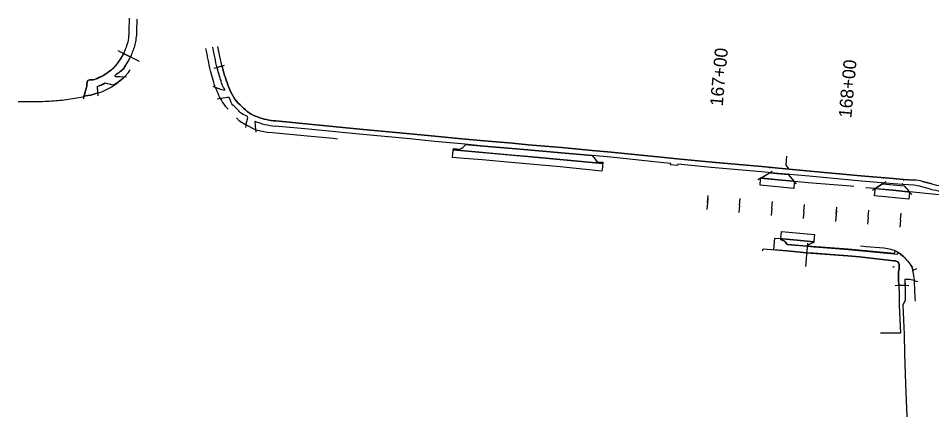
# Model space of a CAD drawing. Extents: x 20499880 to 20505309, y 7953507 to 7955507.
# Drawn here: x 20499880 to 20500587, y 7953843 to 7954151 of the extents above; entities that cross this region are included whole.
import ezdxf

# ---------------------------------------------------------------- set-up
doc = ezdxf.new("R2010")
doc.units = 0
for name, color, linetype in [('Alignment', 7, 'Continuous'), ('Curb', 7, 'Continuous'), ('Draft_0', 7, 'Continuous'), ('Draft_7', 7, 'Continuous'), ('EdgePaved', 7, 'Continuous'), ('Entrance', 7, 'Continuous')]:
    doc.layers.add(name, color=color, linetype=linetype)

msp = doc.modelspace()

# ---------------------------------------------------------------- linework, layer by layer
at = {"layer": 'Alignment'}
for p, q in [((20500413.4, 7954008.91), (20500413.9, 7954014.35)), ((20500413.4, 7954008.91), (20500412.91, 7954003.47)), ((20500512.99, 7953999.8), (20500513.49, 7954005.24)), ((20500512.99, 7953999.8), (20500512.49, 7953994.36))]:
    msp.add_line(p, q, dxfattribs=at)
at = {"layer": 'Curb'}
for p, q in [((20499973.8, 7954117.93), (20499957.3, 7954126.26)), ((20500031.67, 7954112.87), (20500039.61, 7954115.18)), ((20500032.78, 7954097.95), (20500031.03, 7954098.58)), ((20500033.16, 7954096.5), (20500032.53, 7954098.14)), ((20500032.78, 7954097.95), (20500036.7, 7954096.53)), ((20500036.7, 7954096.53), (20500039.61, 7954095.78)), ((20500036.59, 7954089.25), (20500034.08, 7954088.79)), ((20500036.43, 7954089.27), (20500035.86, 7954090.38)), ((20500038.72, 7954089.64), (20500036.59, 7954089.25)), ((20500042.12, 7954090.26), (20500038.72, 7954089.64)), ((20500042.47, 7954081.07), (20500040.13, 7954083.51)), ((20500051.42, 7954071.89), (20500048.99, 7954074.45)), ((20500057.07, 7954071.57), (20500057.64, 7954074.45)), ((20500056.14, 7954068.86), (20500051.42, 7954071.89)), ((20500056.35, 7954068.9), (20500055.82, 7954066.93)), ((20500057.16, 7954068.38), (20500056.14, 7954068.86)), ((20500056.35, 7954068.9), (20500057.07, 7954071.57)), ((20500062.62, 7954065.74), (20500057.16, 7954068.38)), ((20500063.19, 7954071.79), (20500063.48, 7954068.16)), ((20500063.48, 7954068.16), (20500063.67, 7954065.44)), ((20500104.81, 7954065.58), (20500078.93, 7954068.03)), ((20500105.19, 7954069.47), (20500079.37, 7954072)), ((20500144.47, 7954065.69), (20500105.19, 7954069.47)), ((20500063.89, 7954065.16), (20500062.62, 7954065.74)), ((20500063.67, 7954065.44), (20500063.81, 7954063.4)), ((20500103.94, 7954060.16), (20500073.94, 7954063.02)), ((20500123.68, 7954058.39), (20500103.94, 7954060.16)), ((20500143.94, 7954061.83), (20500104.81, 7954065.58)), ((20500183.22, 7954058.05), (20500143.94, 7954061.83)), ((20500183.41, 7954062.13), (20500144.47, 7954065.69)), ((20500202.59, 7954060.17), (20500183.41, 7954062.13)), ((20500223.4, 7954058.24), (20500202.59, 7954060.17)), ((20500127.04, 7954058.02), (20500123.68, 7954058.39)), ((20500202.08, 7954056.17), (20500183.22, 7954058.05)), ((20500222.99, 7954054.19), (20500202.08, 7954056.17)), ((20500240.36, 7954052.62), (20500222.99, 7954054.19)), ((20500240.64, 7954056.62), (20500223.4, 7954058.24)), ((20500262.34, 7954050.65), (20500240.36, 7954052.62)), ((20500262.67, 7954054.79), (20500240.64, 7954056.62)), ((20500274.82, 7954053.54), (20500262.67, 7954054.79)), ((20500300.6, 7954051.37), (20500274.82, 7954053.54)), ((20500274.47, 7954049.57), (20500262.34, 7954050.65)), ((20500300.21, 7954047.31), (20500274.47, 7954049.57)), ((20500324.26, 7954045.4), (20500300.21, 7954047.31)), ((20500324.26, 7954049.21), (20500300.6, 7954051.37)), ((20500338.83, 7954047.76), (20500324.26, 7954049.21)), ((20500338.58, 7954043.89), (20500324.26, 7954045.4)), ((20500377.6, 7954043.89), (20500338.83, 7954047.76)), ((20500377.05, 7954039.84), (20500338.58, 7954043.89)), ((20500385.03, 7954039), (20500377.05, 7954039.84)), ((20500389.99, 7954042.67), (20500377.6, 7954043.89)), ((20500384.97, 7954038.02), (20500385.03, 7954039)), ((20500390.36, 7954037.49), (20500384.97, 7954038.02)), ((20500417.16, 7954040.21), (20500389.99, 7954042.67)), ((20500390.47, 7954038.55), (20500390.36, 7954037.49)), ((20500416.2, 7954036.12), (20500390.47, 7954038.55)), ((20500455.59, 7954036.74), (20500417.16, 7954040.21)), ((20500455.25, 7954032.56), (20500416.2, 7954036.12)), ((20500468.08, 7954031.37), (20500455.25, 7954032.56)), ((20500468.45, 7954035.45), (20500455.59, 7954036.74)), ((20500461.79, 7954036.23), (20500461.15, 7954035.57)), ((20500461.35, 7954031.96), (20500463.43, 7954033.24)), ((20500492.18, 7954029.29), (20500468.08, 7954031.37)), ((20500493.03, 7954033.23), (20500468.45, 7954035.45)), ((20500476.15, 7954030.5), (20500475.41, 7954031.38)), ((20500532.19, 7954029.67), (20500493.03, 7954033.23)), ((20500454.94, 7954028.04), (20500452.54, 7954026.57)), ((20500480.35, 7954025.5), (20500482.16, 7954023.35)), ((20500532.7, 7954025.55), (20500492.18, 7954029.29)), ((20500557.13, 7954027.54), (20500532.19, 7954029.67)), ((20500557.3, 7954023.46), (20500532.7, 7954025.55)), ((20500550.15, 7954028.26), (20500549.36, 7954027.43)), ((20500549.91, 7954024.04), (20500551.64, 7954025.19)), ((20500565.04, 7954026.81), (20500557.13, 7954027.54)), ((20500564.78, 7954022.72), (20500564.01, 7954023.57)), ((20500564.77, 7954026.99), (20500565.43, 7954026.05)), ((20500573.38, 7954026.23), (20500565.04, 7954026.81)), ((20500587.01, 7954023.29), (20500579.82, 7954025.19)), ((20500543.62, 7954019.86), (20500541.28, 7954018.31)), ((20500564.94, 7954022.82), (20500557.3, 7954023.46)), ((20500573.1, 7954022.26), (20500564.94, 7954022.82)), ((20500568.87, 7954018.17), (20500571.53, 7954015.21)), ((20500577.5, 7954021.59), (20500573.1, 7954022.26)), ((20500586.09, 7954019.36), (20500577.5, 7954021.59)), ((20500490.97, 7953977.4), (20500489.33, 7953959.44)), ((20500531.92, 7953975.36), (20500536.23, 7953974.92)), ((20500536.23, 7953974.92), (20500549.98, 7953973.78)), ((20500456, 7953971.64), (20500456.34, 7953972.2)), ((20500456.34, 7953972.2), (20500456.45, 7953973.11)), ((20500456.45, 7953973.11), (20500475.07, 7953971.56)), ((20500475.07, 7953971.56), (20500482.57, 7953970.9)), ((20500482.57, 7953970.9), (20500490.05, 7953970.1)), ((20500490.05, 7953970.1), (20500522.01, 7953967.81)), ((20500522.01, 7953967.81), (20500531.04, 7953966.92)), ((20500531.04, 7953966.92), (20500557.8, 7953963.96)), ((20500561.69, 7953957.72), (20500561.21, 7953955.33)), ((20500561.21, 7953955.33), (20500561.32, 7953949.28)), ((20500572.01, 7953956.44), (20500575.46, 7953957.86)), ((20500572.25, 7953956.44), (20500572.35, 7953955.51)), ((20500572.35, 7953955.51), (20500572.96, 7953952.35)), ((20500561.32, 7953949.28), (20500561.72, 7953938.86)), ((20500572.96, 7953952.35), (20500573.33, 7953949.21)), ((20500573.09, 7953948.62), (20500576.06, 7953947.85)), ((20500573.33, 7953949.21), (20500573.45, 7953948.21)), ((20500573.45, 7953948.21), (20500573.75, 7953940.98)), ((20500569.28, 7953944.81), (20500558.8, 7953944.62)), ((20500561.72, 7953938.86), (20500561.68, 7953929.64)), ((20500573.75, 7953940.98), (20500574, 7953935.24)), ((20500574, 7953935.24), (20500574.22, 7953932.67)), ((20500561.68, 7953929.64), (20500562.76, 7953907.89)), ((20500555.42, 7953907.84), (20500547.33, 7953907.89)), ((20500562.76, 7953907.89), (20500555.42, 7953907.84))]:
    msp.add_line(p, q, dxfattribs=at)
for points in [[(20500324.26, 7954045.4), (20500326.47, 7954042.35), (20500328.82, 7954039.39)], [(20500474.63, 7954044.83), (20500474.23, 7954037.76), (20500476.42, 7954034.69)], [(20500454.94, 7954028.04), (20500461.43, 7954032.01)], [(20500526.74, 7954021.19), (20500524.04, 7954021.59), (20500491.47, 7954024.2), (20500480.9, 7954025.2), (20500479.73, 7954025.35), (20500468.26, 7954026.53), (20500455.73, 7954027.79), (20500454.64, 7954027.86)], [(20500549.91, 7954024.04), (20500543.62, 7954019.86)], [(20500623.83, 7954012.28), (20500622.74, 7954012.45), (20500617.71, 7954012.79), (20500616.66, 7954012.91), (20500590.17, 7954015.26), (20500569.77, 7954017.16), (20500568.64, 7954017.31), (20500556.84, 7954018.48), (20500544.21, 7954019.57), (20500543.25, 7954019.65), (20500536.01, 7954020.3)], [(20500558.83, 7953971.56), (20500557.92, 7953969.58), (20500522.44, 7953972.83), (20500522.44, 7953972.83), (20500522.44, 7953972.83), (20500490.76, 7953975.14)], [(20500573.09, 7953948.62), (20500570.05, 7953949.41), (20500566.23, 7953949.36), (20500566.49, 7953938.8), (20500566.55, 7953933.52), (20500564.62, 7953929.64), (20500565.79, 7953906.99), (20500565.86, 7953892.06), (20500566.7, 7953868.47), (20500567.64, 7953843.31)]]:
    msp.add_lwpolyline(points, dxfattribs=at)
for centre, major_axis, ratio, start_param, end_param in [((20500109.66, 7954126.49), (40.23, -72.37), 0.992173, 4.579645, 4.66041), ((20500101.14, 7954128.27), (47.29, -79.49), 0.816879, 4.717117, 4.7912), ((20500084.23, 7954125.01), (-33.1, -46.68), 0.999978, 0.240316, 0.524068), ((20500118.11, 7954291.87), (234.68, -29.36), 0.985398, 4.603689, 4.647146), ((20500573.68, 7954007.66), (-18.34, 2.97), 0.999975, 4.535868, 4.88891), ((20500597.14, 7954056.56), (38.51, -5.08), 0.998991, 4.555055, 4.97441), ((20500597.28, 7954056.96), (35.13, -2.99), 0.998255, 4.501703, 4.932072)]:
    msp.add_ellipse(centre, major_axis=major_axis, ratio=ratio, start_param=start_param, end_param=end_param, dxfattribs=at)
for points in [[(20500079.37, 7954072), (20500076.84, 7954072.25), (20500072.24, 7954072.87), (20500065.17, 7954075), (20500058.59, 7954077.94), (20500053.14, 7954082.97), (20500047.46, 7954088.68), (20500043.65, 7954095.97), (20500040.93, 7954103.73), (20500038.6, 7954110.8), (20500036.49, 7954119.52), (20500035.2, 7954125.81), (20500034.55, 7954129.61)], [(20500032.53, 7954098.14), (20500032.11, 7954099.24), (20500030.85, 7954103.55), (20500028.82, 7954110.53), (20500027.06, 7954119.46), (20500025.86, 7954125.26), (20500025.3, 7954128.15)], [(20500039.61, 7954095.78), (20500040.72, 7954095.49), (20500037.59, 7954099.54), (20500037.48, 7954102.19), (20500035.92, 7954105.98), (20500034.62, 7954110.99), (20500032.59, 7954118.74), (20500031.3, 7954125.23), (20500030.62, 7954129.18)], [(20500057.64, 7954074.45), (20500057.94, 7954075.94), (20500053.31, 7954076.85), (20500050.72, 7954079.8), (20500047.83, 7954082.99), (20500044.47, 7954085.47), (20500043.88, 7954090.59), (20500042.12, 7954090.26)], [(20500549.98, 7953973.78), (20500553.74, 7953973.46), (20500560.65, 7953971.62), (20500567.85, 7953964.73), (20500571.97, 7953959.08), (20500572.25, 7953956.44)], [(20500557.8, 7953963.96), (20500559.15, 7953963.81), (20500561.09, 7953963.38), (20500562.02, 7953960.23), (20500561.86, 7953958.57), (20500561.69, 7953957.72)], [(20500557.27, 7953959.19), (20500558.37, 7953959.07), (20500557.29, 7953959.31), (20500557.15, 7953959.76), (20500557.11, 7953959.28), (20500556.98, 7953958.67)]]:
    msp.add_open_spline(points, degree=3, dxfattribs=at)
at = {"layer": 'Draft_0'}
for p, q in [((20500033.96, 7954113.54), (20500037.69, 7954114.62)), ((20500036.43, 7954089.27), (20500035.86, 7954090.38)), ((20500579.82, 7954025.19), (20500587.01, 7954023.29))]:
    msp.add_line(p, q, dxfattribs=at)
for points in [[(20499961.14, 7954123.44), (20499961.46, 7954124.16), (20499966.76, 7954121.48)], [(20499957.01, 7954108.81), (20499955.31, 7954107.41), (20499954.9, 7954106.96), (20499954.84, 7954106.56), (20499955.33, 7954106.42), (20499962.32, 7954106.08), (20499961.36, 7954105.15), (20499957.42, 7954101.94), (20499954.09, 7954099.57), (20499946.85, 7954101.14)], [(20499941.16, 7954098.73), (20499941.17, 7954098.56), (20499941.45, 7954093.57), (20499940.24, 7954093.1), (20499936.25, 7954092.06), (20499932.09, 7954091.32), (20499930.94, 7954090.98), (20499931.74, 7954094.16), (20499932.39, 7954096.29), (20499932.39, 7954096.29), (20499932.39, 7954096.29), (20499932.39, 7954096.29), (20499932.39, 7954096.29), (20499932.39, 7954096.29), (20499932.39, 7954096.29), (20499933.1, 7954098.63), (20499933.16, 7954098.85), (20499933.21, 7954099.39), (20499933.47, 7954102.54)], [(20500033.16, 7954096.5), (20500032.58, 7954098.02), (20500036.7, 7954096.53), (20500039.61, 7954095.78)], [(20500042.12, 7954090.26), (20500038.72, 7954089.64), (20500036.46, 7954089.22)], [(20500063.19, 7954071.79), (20500063.48, 7954068.16), (20500063.68, 7954065.26), (20500062.62, 7954065.74), (20500057.16, 7954068.38), (20500056.32, 7954068.77), (20500057.07, 7954071.57), (20500057.64, 7954074.45)], [(20500586.09, 7954019.36), (20500577.5, 7954021.59), (20500573.1, 7954022.26), (20500564.94, 7954022.82), (20500557.3, 7954023.46), (20500532.7, 7954025.55), (20500492.18, 7954029.29), (20500468.08, 7954031.37), (20500455.25, 7954032.56), (20500416.2, 7954036.12), (20500390.47, 7954038.55), (20500390.36, 7954037.49), (20500384.97, 7954038.02), (20500385.03, 7954039), (20500377.05, 7954039.84), (20500338.58, 7954043.89), (20500324.26, 7954045.4), (20500300.21, 7954047.31), (20500274.47, 7954049.57), (20500262.34, 7954050.65), (20500240.36, 7954052.62), (20500222.99, 7954054.19), (20500202.08, 7954056.17), (20500183.22, 7954058.05), (20500143.94, 7954061.83), (20500104.81, 7954065.58), (20500078.93, 7954068.03)], [(20500079.37, 7954072), (20500105.19, 7954069.47), (20500144.47, 7954065.69), (20500183.41, 7954062.13), (20500202.59, 7954060.17), (20500223.4, 7954058.24), (20500240.64, 7954056.62), (20500262.67, 7954054.79), (20500274.82, 7954053.54), (20500300.6, 7954051.37), (20500324.26, 7954049.21), (20500338.83, 7954047.76), (20500377.6, 7954043.89), (20500389.99, 7954042.67), (20500417.16, 7954040.21), (20500455.59, 7954036.74), (20500468.45, 7954035.45), (20500493.03, 7954033.23), (20500532.19, 7954029.67), (20500557.13, 7954027.54), (20500565.04, 7954026.81), (20500573.38, 7954026.23)], [(20500226.17, 7954053.61), (20500226.19, 7954053.9), (20500240.36, 7954052.62), (20500262.34, 7954050.65), (20500274.47, 7954049.57), (20500300.21, 7954047.31), (20500324.26, 7954045.4), (20500326.47, 7954042.35), (20500327.95, 7954040.49), (20500332.46, 7954040.02), (20500332.36, 7954039.03), (20500274.52, 7954044.5), (20500264.53, 7954045.4), (20500264.53, 7954045.39), (20500216.77, 7954049.62), (20500216.85, 7954050.61), (20500221.68, 7954050.2)], [(20500557.8, 7953963.96), (20500531.04, 7953966.92), (20500522.01, 7953967.81), (20500505.38, 7953969), (20500495.43, 7953969.69), (20500490.3, 7953970.08), (20500474.76, 7953971.59), (20500464.8, 7953972.41), (20500465.56, 7953981.45), (20500470.32, 7953981.05), (20500470.25, 7953980.12), (20500471.2, 7953979.94), (20500472.05, 7953979.62), (20500472.72, 7953979.23), (20500473.32, 7953978.76), (20500474, 7953978.02), (20500474.91, 7953976.7), (20500475.22, 7953976.57), (20500490.76, 7953975.14), (20500495.74, 7953974.69), (20500506.03, 7953973.91), (20500522.38, 7953972.67), (20500557.88, 7953969.14), (20500560.46, 7953968.92)], [(20500470.25, 7953980.12), (20500470.32, 7953981.05), (20500471.51, 7953980.94), (20500482.83, 7953979.76), (20500495.78, 7953978.61), (20500495.57, 7953977.71)], [(20500490.24, 7953975.19), (20500475.22, 7953976.57), (20500474.91, 7953976.7), (20500474.39, 7953977.43)], [(20500491.09, 7953975.67), (20500490.79, 7953975.42), (20500490.82, 7953975.77)], [(20500572.25, 7953956.44), (20500572.35, 7953955.51), (20500572.96, 7953952.35), (20500573.33, 7953949.21), (20500573.41, 7953948.54), (20500570.05, 7953949.41), (20500566.23, 7953949.36), (20500566.34, 7953944.76), (20500561.5, 7953944.67), (20500561.32, 7953949.28), (20500561.21, 7953955.33), (20500561.69, 7953957.72)]]:
    msp.add_lwpolyline(points, dxfattribs=at)
for points in [[(20500331.81, 7954033.26), (20500299.37, 7954036.41), (20500261.45, 7954039.86), (20500239.04, 7954041.83), (20500221.79, 7954043.31), (20500216.24, 7954043.84), (20500216.52, 7954046.82), (20500216.69, 7954048.75), (20500216.69, 7954048.75), (20500216.69, 7954048.75), (20500216.69, 7954048.75), (20500216.69, 7954048.75), (20500216.77, 7954049.62), (20500274.52, 7954044.5), (20500332.36, 7954039.03), (20500332.27, 7954038.08), (20500332.27, 7954038.08), (20500332.1, 7954036.25)], [(20500476, 7954030.69), (20500480.57, 7954025.24), (20500479.73, 7954025.35), (20500468.26, 7954026.53), (20500455.73, 7954027.79), (20500454.64, 7954027.86), (20500461.39, 7954031.99)], [(20500454.11, 7954022.3), (20500454.57, 7954027.08), (20500454.64, 7954027.86), (20500468.26, 7954026.53), (20500479.73, 7954025.35), (20500480.57, 7954025.24), (20500480.71, 7954025.23), (20500480.64, 7954024.46), (20500480.18, 7954019.66)], [(20500569.26, 7954011.6), (20500542.78, 7954014), (20500543.22, 7954018.85), (20500543.3, 7954019.65), (20500556.84, 7954018.48), (20500568.64, 7954017.31), (20500569.77, 7954017.16), (20500569.7, 7954016.4)], [(20500565.58, 7954021.83), (20500569.15, 7954017.86), (20500569.77, 7954017.16), (20500569.77, 7954017.17), (20500568.64, 7954017.31), (20500556.84, 7954018.48), (20500544.21, 7954019.57), (20500543.29, 7954019.65), (20500548.8, 7954023.31)], [(20500495.74, 7953978.6), (20500495.74, 7953978.6), (20500482.83, 7953979.76), (20500471.51, 7953980.94), (20500470.32, 7953981.05), (20500470.79, 7953986.65), (20500470.82, 7953986.65), (20500496.22, 7953984.29), (20500495.81, 7953979.43)]]:
    msp.add_lwpolyline(points, close=True, dxfattribs=at)
for centre, radius, start, end in [((20499938.26, 7954133.49), 25, 320.60131, 336.27547), ((20499950.36, 7954121.33), 14.18, 297.96753, 331.9374), ((20499934.77, 7954102.33), 1.32, 92.15115, 170.94232), ((20499925.64, 7954141.96), 46, 291.46899, 297.45355), ((20500218.11, 7954059.54), 10, 290.88202, 323.65709), ((20500497.59, 7953968.41), 10, 132.59939, 137.31599)]:
    msp.add_arc(centre, radius, start, end, dxfattribs=at)
for centre, major_axis, ratio, start_param, end_param in [((20499929.5, 7954136.97), (37.95, 12.67), 0.999322, 4.686181, 4.720754), ((20500109.66, 7954126.49), (40.23, -72.37), 0.992173, 4.579645, 4.66041), ((20500101.14, 7954128.27), (47.29, -79.49), 0.816879, 4.717117, 4.71772), ((20500084.23, 7954125.01), (-33.1, -46.68), 0.999978, 0.240316, 0.524068), ((20500573.68, 7954007.66), (-18.34, 2.97), 0.999975, 4.535868, 4.88891), ((20500597.14, 7954056.56), (38.51, -5.08), 0.998991, 4.555055, 4.97441), ((20500469.72, 7953974.79), (5.36, -0.21), 0.998982, 0.555677, 1.511678), ((20500495.96, 7953970.85), (-4.8, -4.95), 0.994681, 3.971942, 4.701982)]:
    msp.add_ellipse(centre, major_axis=major_axis, ratio=ratio, start_param=start_param, end_param=end_param, dxfattribs=at)
for points, degree in [([(20499955.38, 7954114.64), (20499956.18, 7954115.58), (20499956.88, 7954116.6), (20499957.58, 7954117.63)], 2), ([(20499963.46, 7954115.74), (20499963.25, 7954115.37), (20499963.06, 7954115.01), (20499962.87, 7954114.66)], 2), ([(20499966.76, 7954121.48), (20499966.38, 7954120.68), (20499965.39, 7954118.73), (20499964.06, 7954116.79), (20499963.46, 7954115.74)], 3), ([(20499937.81, 7954103.84), (20499939.82, 7954104), (20499942.48, 7954105.58), (20499946.55, 7954107.35), (20499949.31, 7954109.4), (20499952.15, 7954111.47), (20499954.19, 7954113.25), (20499955.38, 7954114.64)], 3), ([(20500034.94, 7954109.75), (20500034.61, 7954111), (20500034.28, 7954112.27), (20500033.96, 7954113.54)], 2), ([(20500039.61, 7954095.78), (20500040.72, 7954095.49), (20500037.59, 7954099.54), (20500037.48, 7954102.19), (20500035.92, 7954105.98), (20500035.27, 7954108.49), (20500034.94, 7954109.75)], 3), ([(20500037.69, 7954114.62), (20500038.01, 7954113.35), (20500038.34, 7954112.09), (20500038.7, 7954110.83)], 2), ([(20500038.7, 7954110.83), (20500039.4, 7954108.37), (20500040.93, 7954103.73), (20500043.65, 7954095.97), (20500047.46, 7954088.68), (20500053.14, 7954082.97), (20500058.59, 7954077.94), (20500065.17, 7954075), (20500072.24, 7954072.87), (20500076.84, 7954072.25), (20500079.37, 7954072)], 3), ([(20499934.72, 7954103.65), (20499934.98, 7954103.79), (20499937.78, 7954103.83), (20499937.81, 7954103.84)], 2), ([(20500057.64, 7954074.45), (20500057.94, 7954075.94), (20500053.31, 7954076.85), (20500050.72, 7954079.8), (20500047.83, 7954082.99), (20500044.47, 7954085.47), (20500043.88, 7954090.59), (20500042.12, 7954090.26)], 3), ([(20500560.46, 7953968.92), (20500560.74, 7953969.37), (20500561.04, 7953969.85), (20500561.29, 7953970.25)], 2), ([(20500561.29, 7953970.25), (20500563.22, 7953969.16), (20500565.83, 7953966.67), (20500568.27, 7953963.79)], 2), ([(20500561.69, 7953957.72), (20500561.86, 7953958.57), (20500562.02, 7953960.23), (20500561.09, 7953963.38), (20500559.15, 7953963.81), (20500557.8, 7953963.96)], 3), ([(20500568.27, 7953963.79), (20500570.17, 7953961.55), (20500571.97, 7953959.08), (20500572.25, 7953956.44)], 2)]:
    msp.add_open_spline(points, degree=degree, dxfattribs=at)
at = {"layer": 'Draft_7'}
for p, q in [((20499962.13, 7954105.87), (20499965.36, 7954109.47)), ((20499965.36, 7954109.47), (20499966.74, 7954111.59)), ((20499954.98, 7954100.1), (20499957.42, 7954101.94)), ((20499957.42, 7954101.94), (20499961.36, 7954105.15)), ((20499961.36, 7954105.15), (20499962.13, 7954105.87)), ((20499953.86, 7954099.43), (20499954.98, 7954100.1)), ((20499931.13, 7954091.03), (20499932.09, 7954091.32)), ((20499932.09, 7954091.32), (20499936.25, 7954092.06)), ((20499936.25, 7954092.06), (20499940.24, 7954093.1)), ((20499940.24, 7954093.1), (20499941.41, 7954093.55)), ((20499880.09, 7954086.98), (20499892, 7954087.05)), ((20500490.41, 7953975.1), (20500491.09, 7953975.67)), ((20500495.57, 7953977.71), (20500495.83, 7953978.81))]:
    msp.add_line(p, q, dxfattribs=at)
for centre, major_axis, ratio, start_param, end_param in [((20499930.67, 7954132.39), (40.08, -4.2), 0.999939, 5.086579, 5.429975), ((20500495.96, 7953970.85), (-4.8, -4.95), 0.994681, 3.971942, 4.701982)]:
    msp.add_ellipse(centre, major_axis=major_axis, ratio=ratio, start_param=start_param, end_param=end_param, dxfattribs=at)
msp.add_open_spline([(20499892, 7954087.05), (20499896.49, 7954087.08), (20499905.93, 7954087.22), (20499918.74, 7954088.73), (20499927.83, 7954090.04), (20499931.13, 7954091.03)], degree=3, dxfattribs=at)
at = {"layer": 'EdgePaved'}
for p, q in [((20499965.84, 7954151.39), (20499965.62, 7954141.64)), ((20499971.85, 7954150.78), (20499971.65, 7954141.37)), ((20499933.47, 7954102.54), (20499933.16, 7954098.85)), ((20499955.33, 7954106.42), (20499958.9, 7954106.27)), ((20499958.9, 7954106.27), (20499963.87, 7954106)), ((20499932.39, 7954096.29), (20499931.74, 7954094.16)), ((20499933.16, 7954098.85), (20499932.39, 7954096.29)), ((20499941.16, 7954098.73), (20499941.32, 7954095.21)), ((20499941.32, 7954095.21), (20499941.62, 7954091.34)), ((20499951.63, 7954100.09), (20499947.17, 7954101.11)), ((20499954.38, 7954099.51), (20499951.63, 7954100.09)), ((20499931.74, 7954094.16), (20499930.43, 7954088.96))]:
    msp.add_line(p, q, dxfattribs=at)
msp.add_ellipse((20499929.5, 7954136.97), major_axis=(37.95, 12.67), ratio=0.999322, start_param=4.686181, end_param=4.847898, dxfattribs=at)
for points in [[(20499965.62, 7954141.64), (20499965.55, 7954138.36), (20499965.35, 7954134.38), (20499963.48, 7954128.59), (20499961.95, 7954125.3), (20499960.36, 7954121.61), (20499958.13, 7954118.54), (20499955.56, 7954114.44), (20499952.15, 7954111.47), (20499949.31, 7954109.4), (20499946.55, 7954107.35), (20499942.48, 7954105.58), (20499938.66, 7954103.3), (20499933.6, 7954104.04), (20499933.47, 7954102.54)], [(20499971.65, 7954141.37), (20499971.6, 7954139.16), (20499971.17, 7954135.5), (20499970.5, 7954130.98), (20499968.99, 7954126.54), (20499967.42, 7954122.74), (20499965.39, 7954118.73), (20499962.76, 7954114.89), (20499961.58, 7954111.24), (20499953.35, 7954106.5), (20499955.33, 7954106.42)]]:
    msp.add_open_spline(points, degree=3, dxfattribs=at)
at = {"layer": 'Entrance'}
for p, q in [((20500413.68, 7954011.96), (20500413.12, 7954005.86)), ((20500413.68, 7954011.96), (20500413.12, 7954005.86)), ((20500438.3, 7954006.63), (20500438.8, 7954012.07)), ((20500463.2, 7954004.36), (20500463.69, 7954009.79)), ((20500438.3, 7954006.63), (20500437.8, 7954001.2)), ((20500463.2, 7954004.36), (20500462.7, 7953998.92)), ((20500488.09, 7954002.08), (20500488.59, 7954007.51)), ((20500513.27, 7954002.85), (20500512.71, 7953996.75)), ((20500513.27, 7954002.85), (20500512.71, 7953996.75)), ((20500537.88, 7953997.52), (20500538.38, 7954002.96)), ((20500488.09, 7954002.08), (20500487.59, 7953996.64)), ((20500537.88, 7953997.52), (20500537.39, 7953992.08)), ((20500562.78, 7953995.24), (20500562.28, 7953989.81)), ((20500562.78, 7953995.24), (20500563.28, 7954000.68))]:
    msp.add_line(p, q, dxfattribs=at)

# ---------------------------------------------------------------- texts
for s, p in [('167+00', (20500425.23, 7954083.14)), ('168+00', (20500524.81, 7954074.03))]:
    msp.add_text(s, height=10.02, rotation=84.77145, dxfattribs=at).set_placement(p)

doc.saveas('drawing.dxf')
